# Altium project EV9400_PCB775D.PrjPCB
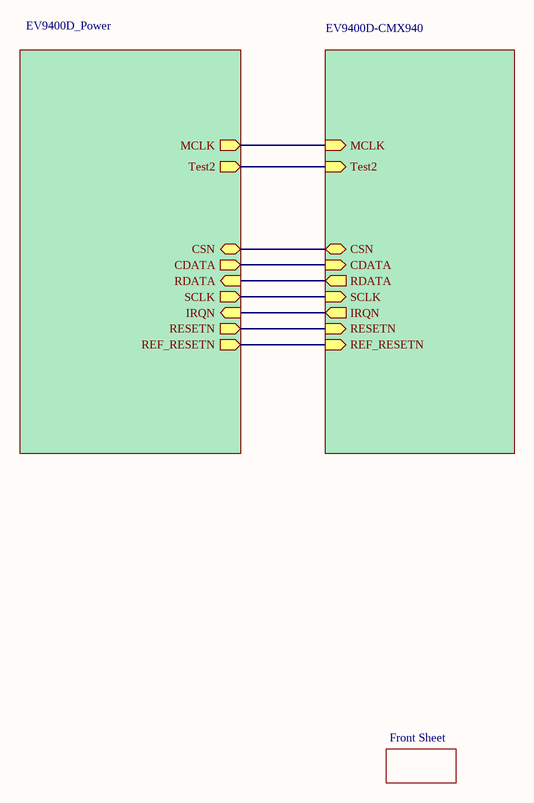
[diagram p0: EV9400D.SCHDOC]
4 sheets, 203 parts. Net scope: hierarchical (ports join the sheet entries above them; power ports are global).
Board file: EV9400D_PCB775D.PCBDOC
Sheets:
  EV9400D.SCHDOC
    EV9400D_Power = EV9400D_Power.SCHDOC
    EV9400D-CMX940 = EV9400D-CMX940.SCHDOC
    Front Sheet = EV9400D_FrontSheet.SchDoc

## Sheet EV9400D.SCHDOC: EV9400
size A4; Date: 09/04/2020; DrawnBy: RAS; Engineer: JLF; Organization: CML Microcircuits UK Ltd; Revision: D02; SheetNumber: 2; SheetTotal: 4; ModifiedBy: RAS; ProjectNo: z206; PageSetup: Record=PageOptions¦CenterHorizontal=True¦CenterVertical=True¦PrintScale=0.71¦XCorrection=1.00¦YCorrection=1.00¦PrintKind=1¦BorderSize=5000000¦LeftOffset=0¦BottomOffset=0¦Orientation=2¦PaperLength=1000¦PaperWidth=1000¦Scale=100¦PaperSource=15¦PrintQuality=600¦MediaType=1¦DitherType=10¦PaperKind=A3¦PrintScaleMode=1

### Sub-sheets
EV9400D-CMX940 = EV9400D-CMX940.SCHDOC: MCLK (in), CSN, CDATA (in), RDATA (out), SCLK (in), IRQN (out), RESETN (in), REF_RESETN (in), Test2 (in)
EV9400D_Power = EV9400D_Power.SCHDOC: MCLK (out), CSN, CDATA (out), RDATA (in), SCLK (out), IRQN (in), RESETN (out), REF_RESETN (out), Test2 (out)
Front Sheet = EV9400D_FrontSheet.SchDoc: no entries

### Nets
CDATA: sheet EV9400D_Power/CDATA, sheet EV9400D-CMX940/CDATA
CSN: sheet EV9400D_Power/CSN, sheet EV9400D-CMX940/CSN
IRQN: sheet EV9400D_Power/IRQN, sheet EV9400D-CMX940/IRQN
MCLK: sheet EV9400D_Power/MCLK, sheet EV9400D-CMX940/MCLK
RDATA: sheet EV9400D_Power/RDATA, sheet EV9400D-CMX940/RDATA
REF_RESETN: sheet EV9400D_Power/REF_RESETN, sheet EV9400D-CMX940/REF_RESETN
RESETN: sheet EV9400D_Power/RESETN, sheet EV9400D-CMX940/RESETN
SCLK: sheet EV9400D_Power/SCLK, sheet EV9400D-CMX940/SCLK
Test2: sheet EV9400D_Power/Test2, sheet EV9400D-CMX940/Test2

## Sheet EV9400D_Power.SCHDOC: EV9400 Power
size A3; Date: 09/04/2020; DrawnBy: RAS; Engineer: JLF; Organization: CML Microcircuits UK Ltd; Revision: D02; SheetNumber: 3; SheetTotal: 4; ModifiedBy: RAS; ProjectNo: z206; PageSetup: Record=PageOptions¦CenterHorizontal=True¦CenterVertical=True¦PrintScale=1.02¦XCorrection=1.00¦YCorrection=1.00¦PrintKind=1¦BorderSize=5000000¦LeftOffset=0¦BottomOffset=0¦Orientation=2¦PaperLength=5940¦PaperWidth=4200¦Scale=100¦PaperSource=7¦PrintQuality=600¦MediaType=1¦DitherType=10¦PaperKind=A2¦PrintScaleMode=1
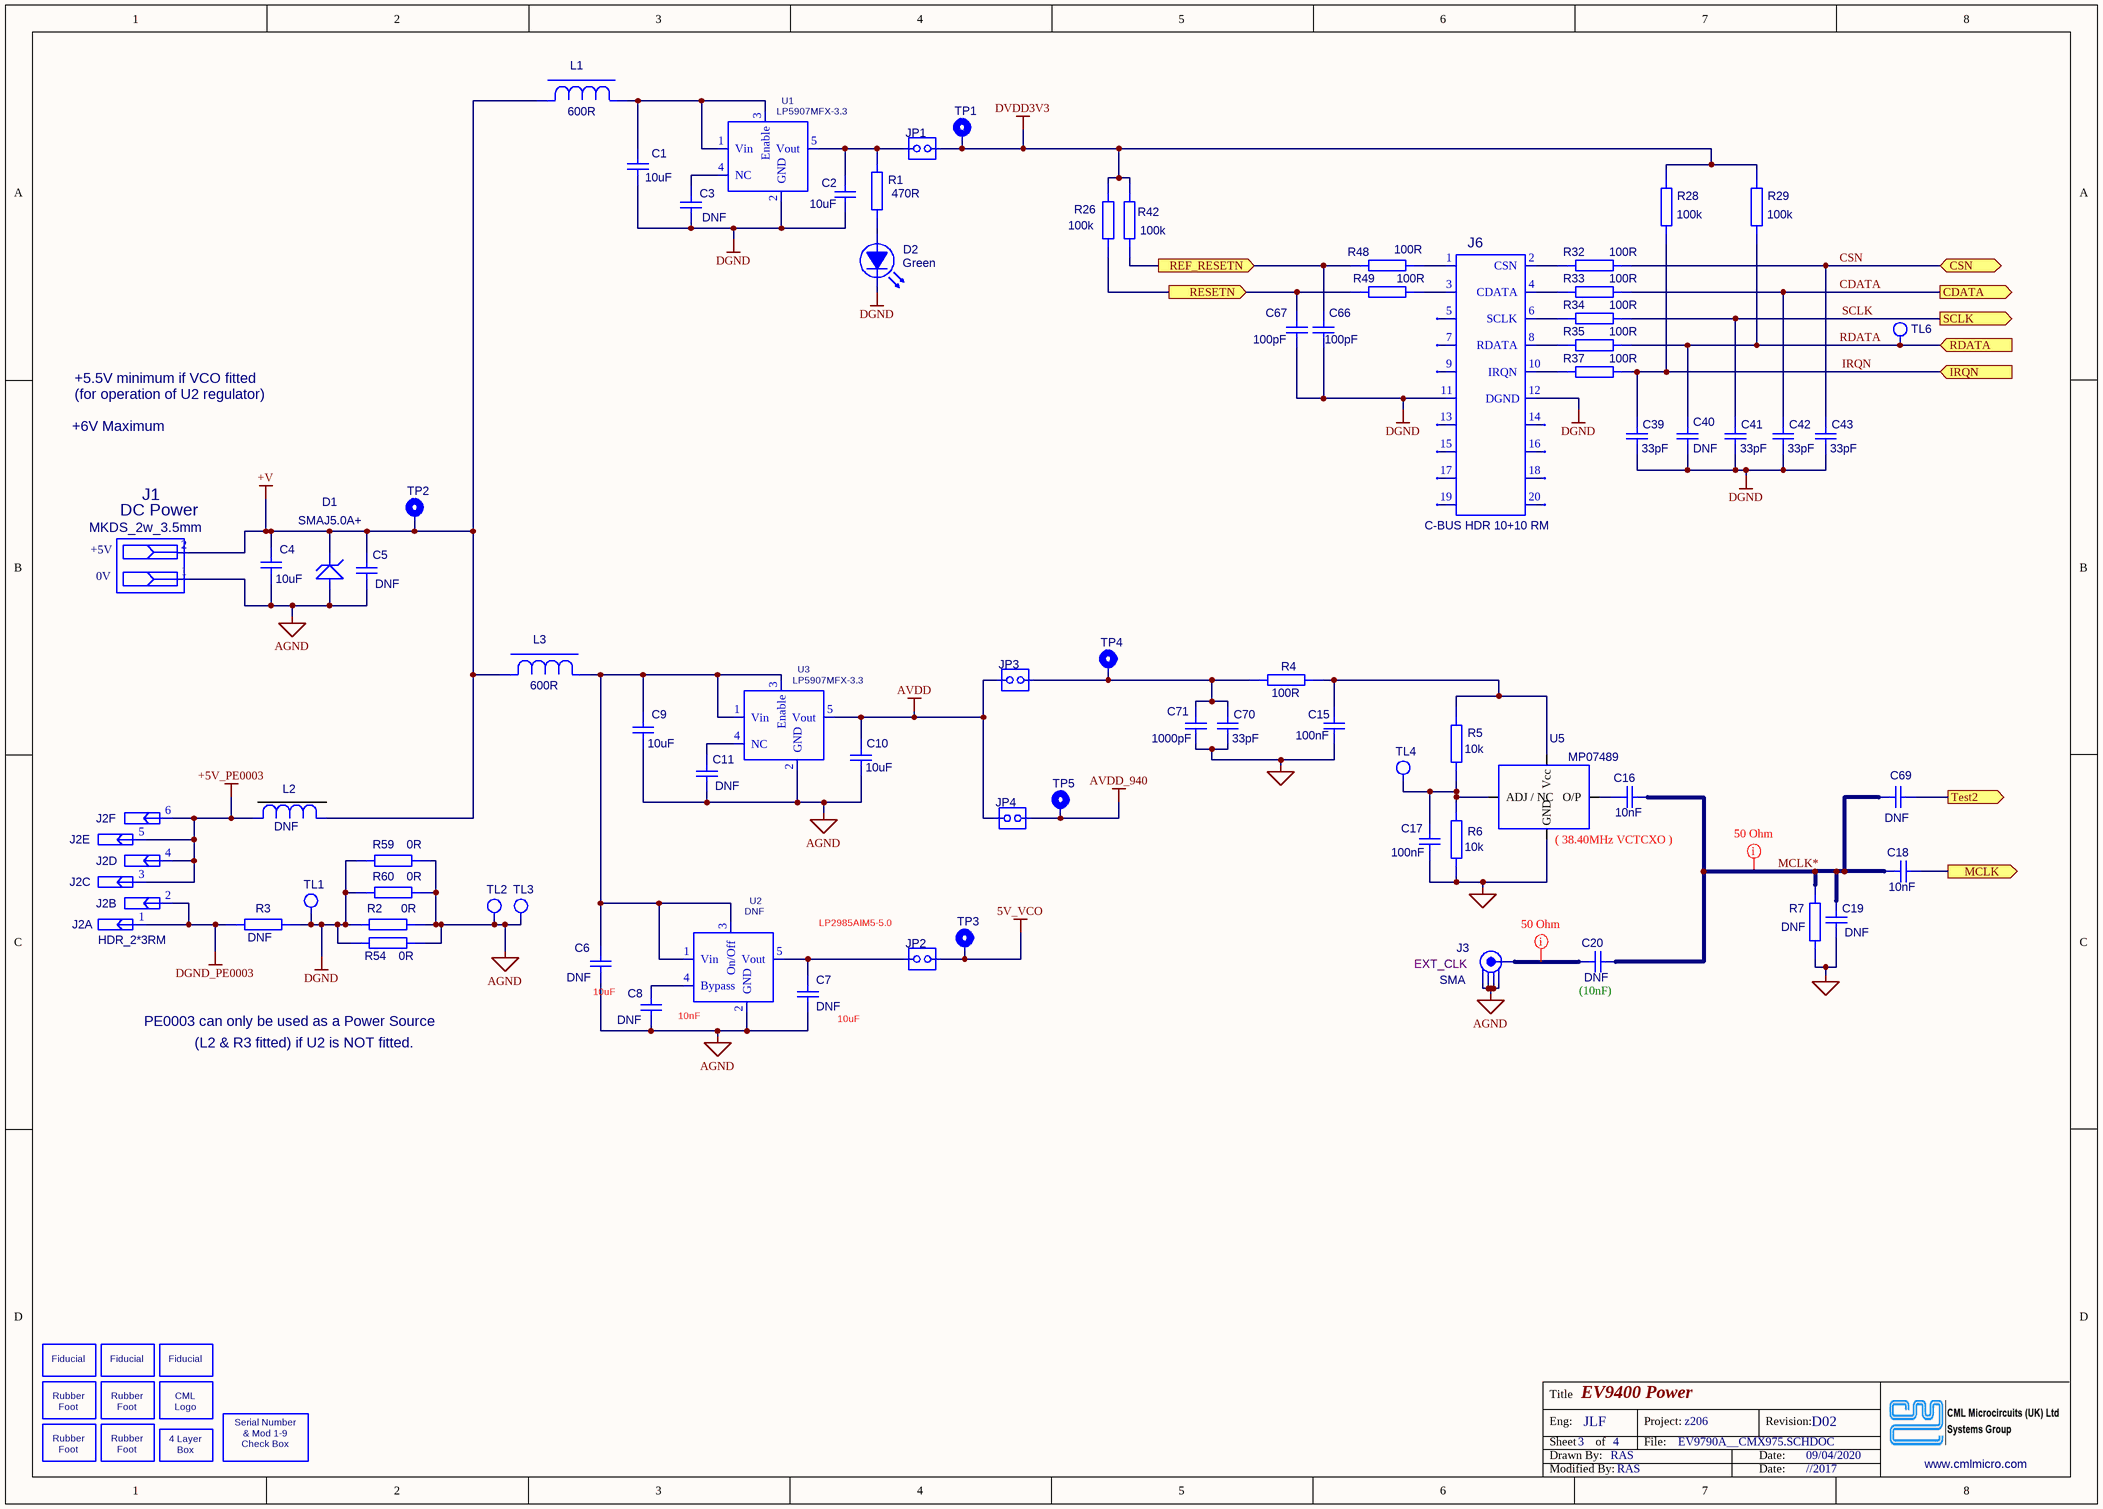
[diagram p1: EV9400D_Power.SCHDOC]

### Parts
C1  10uF  [0805COM]
C2  10uF  [0805COM]
C3  DNF  [0402COM]
C4  10uF  [0805COM]
C5  DNF  [0805COM]
C6  DNF  [0805COM]
C7  DNF  [0805COM]
C8  DNF  [0402COM]
C9  10uF  [0805COM]
C10  10uF  [0805COM]
C11  DNF  [0402COM]
C15  100nF  [0402COM]
C16  10nF  [0402COM]
C17  100nF  [0402COM]
C18  10nF  [0402COM]
C19  DNF  [0402COM]
C20  DNF  [0402COM]
C39  33pF  [0402COM]
C40  DNF  [0402COM]
C41  33pF  [0402COM]
C42  33pF  [0402COM]
C43  33pF  [0402COM]
C66  100pF  [0402COM]
C67  100pF  [0402COM]
C69  DNF  [0402COM]
C70  33pF  [0402COM]
C71  1000pF  [0402COM]
D1  SMAJ5.0A+  [DO-214AC SMA]
D2  Green  [LED0603]
FID1  Fiducial  [1.5MM Fiducial]  (value not drawn)  (no BOM)
FID2  Fiducial  [1.5MM Fiducial]  (value not drawn)  (no BOM)
FID3  Fiducial  [1.5MM Fiducial]  (value not drawn)  (no BOM)
FOOT1  Foot  [FOOT]  (value not drawn)
FOOT2  Foot  [FOOT]  (value not drawn)
FOOT3  Foot  [FOOT]  (value not drawn)
FOOT4  Foot  [FOOT]  (value not drawn)
J1  MKDS_2w_3.5mm  [MKDS_2]
J2  HDR_2*3RM  [IDC6RM]  (value not drawn)  (parts A,B,C,D,E,F of 6)
J3  SMA  SignalName: EXT_CLK  [SMA]
J6  C-BUS HDR 10+10 RM  [IDC20RM]
JP1  Jumper2  [JMP2]  (value not drawn)
JP2  DNF  [JMP2]  (value not drawn)  (no BOM)
JP3  Jumper2  [JMP2]  (value not drawn)
JP4  Jumper2  [JMP2]  (value not drawn)
L1  600R  [0603COM]
L2  DNF  [0603COM]
L3  600R  [0603COM]
LAY1  4_LAYER_BOX  [4_LAYER_BOX]  (value not drawn)  (no BOM)
LOGO1  CML_LOGO  [CML_LOGO]  (value not drawn)  (no BOM)
MODBO1  8 Mod Box  [SERIAL_AND_MOD]  (value not drawn)  (no BOM)
P1  PCB Pad  [TINYPAD]  (value not drawn)  (no BOM)
P2  PCB Pad  [TINYPAD]  (value not drawn)  (no BOM)
P3  PCB Pad  [TINYPAD]  (value not drawn)  (no BOM)
P4  PCB Pad  [TINYPAD]  (value not drawn)  (no BOM)
P5  PCB Pad  [TINYPAD]  (value not drawn)  (no BOM)
P6  PCB Pad  [TINYPAD]  (value not drawn)  (no BOM)
P7  PCB Pad  [TINYPAD]  (value not drawn)  (no BOM)
P8  PCB Pad  [TINYPAD]  (value not drawn)  (no BOM)
P9  PCB Pad  [TINYPAD]  (value not drawn)  (no BOM)
P10  PCB Pad  [TINYPAD]  (value not drawn)  (no BOM)
P11  PCB Pad  [TINYPAD]  (value not drawn)  (no BOM)
R1  470R  [0402COM]
R2  0R  [0402COM]
R3  DNF  [0402COM]
R4  100R  [0402COM]
R5  10k  [0402COM]
R6  10k  [0402COM]
R7  DNF  [0402COM]
R26  100k  [0402COM]
R28  100k  [0402COM]
R29  100k  [0402COM]
R32  100R  [0402COM]
R33  100R  [0402COM]
R34  100R  [0402COM]
R35  100R  [0402COM]
R37  100R  [0402COM]
R42  100k  [0402COM]
R48  100R  [0402COM]
R49  100R  [0402COM]
R54  0R  [0402COM]
R59  0R  [0402COM]
R60  0R  [0402COM]
TL1  1.5mm testloop (Y)  [TESTLOOP_1.0MM]  (value not drawn)
TL2  1.5mm testloop (Y)  [TESTLOOP_1.0MM]  (value not drawn)
TL3  1.5mm testloop (Y)  [TESTLOOP_1.0MM]  (value not drawn)
TL4  1.5mm testloop (Y)  [TESTLOOP_1.0MM]  (value not drawn)
TL6  1.5mm testloop (Y)  [TESTLOOP_1.0MM]  (value not drawn)
TP1  DVDD3V3  [1.5MM TSTPOINTV]  (value not drawn)  (no BOM)
TP2  +V  [1.5MM TSTPOINTV]  (value not drawn)  (no BOM)
TP3  5V_VCO  [1.5MM TSTPOINTV]  (value not drawn)  (no BOM)
TP4  AVDD  [1.5MM TSTPOINTV]  (value not drawn)  (no BOM)
TP5  AVDD_940  [1.5MM TSTPOINTV]  (value not drawn)  (no BOM)
U1  LP5907MFX-3.3  [SOT23-5]
U2  DNF  [SOT23-5]  (no BOM)
U3  LP5907MFX-3.3  [SOT23-5]
U5  MP07489  [GTXO-74]

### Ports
CDATA (out), CSN, IRQN (in), MCLK (out), RDATA (in), REF_RESETN (out), RESETN (out), SCLK (out), Test2 (out)

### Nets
5V_VCO: JP2.2 TP3.1
+5V_PE0003: J2.3 J2.4 J2.5 J2.6 L2.1
+V: C4.2 C5.2 D1.1(K) J1.2 L1.1 L2.2 L3.1 TP2.1
AGND: C4.1 C5.1 C6.1 C7.2 C8.2 C9.1 C10.2 C11.2 C15.2 C17.1 C19.2 C70.2 C71.2 D1.2(A) J1.1 J3.2(GND) J3.3(GND) J3.4(GND) J3.5(GND) R2.1 R6.2 R7.1 R54.1 R59.1 R60.1 TL2.1 TL3.1 U2.2(GND) U3.2(GND) U5.2(GND)
AVDD: C10.1 JP3.1 JP4.1 U3.5(Vout)
AVDD_940: JP4.2 TP5.1
DGND: C1.1 C2.2 C3.2 C39.2 C40.2 C41.2 C42.2 C43.2 C66.2 C67.2 D2.2(Cathode) J6.11(DGND) J6.12(DGND) R2.2 R3.1 R54.2 R59.2 R60.2 TL1.1 U1.2(GND)
DGND_PE0003: J2.1 J2.2 R3.2
DVDD3V3: JP1.2 R26.2 R28.2 R29.2 R42.2 TP1.1
CDATA: C42.1 R33.1 ; port CDATA
CSN: C43.1 R32.1 ; port CSN
IRQN: C39.1 R28.1 R37.1 ; port IRQN
MCLK: C18.2 ; port MCLK
MCLK*: C16.2 C18.1 C19.1 C20.2 C69.1 R7.2
RDATA: C40.1 R29.1 R35.1 TL6.1 ; port RDATA
REF_RESETN: C66.1 R42.1 R48.2 ; port REF_RESETN
RESETN: C67.1 R26.1 R49.2 ; port RESETN
SCLK: C41.1 R34.1 ; port SCLK
Test2: C69.2 ; port Test2
NetC1_2: C1.2 L1.2 U1.1(Vin) U1.3(Enable)
NetC2_1: C2.1 JP1.1 R1.1 U1.5(Vout)
NetC3_1: C3.1 U1.4(NC)
NetC6_2: C6.2 C9.2 L3.2 U2.1(Vin) U2.3(On/Off) U3.1(Vin) U3.3(Enable)
NetC7_1: C7.1 JP2.1 U2.5(Vout)
NetC8_1: C8.1 U2.4(Bypass)
NetC11_1: C11.1 U3.4(NC)
NetC15_1: C15.1 R4.1 R5.1 U5.4(Vcc)
NetC16_1: C16.1 U5.3(O/P)
NetC17_2: C17.2 R5.2 R6.1 TL4.1 U5.1(ADJ_/_NC)
NetC20_1: C20.1 J3.1(SIG)
NetC70_1: C70.1 C71.1 JP3.2 R4.2 TP4.1
NetD2_1: D2.1(Anode) R1.2
NetJ6_1: J6.1 R48.1
NetJ6_2: J6.2(CSN) R32.2
NetJ6_3: J6.3 R49.1
NetJ6_4: J6.4(CDATA) R33.2
NetJ6_5: J6.5 P1.1
NetJ6_6: J6.6(SCLK) R34.2
NetJ6_7: J6.7 P2.1
NetJ6_8: J6.8(RDATA) R35.2
NetJ6_9: J6.9 P3.1
NetJ6_10: J6.10(IRQN) R37.2
NetJ6_13: J6.13 P4.1
NetJ6_14: J6.14 P11.1
NetJ6_15: J6.15 P5.1
NetJ6_16: J6.16 P10.1
NetJ6_17: J6.17 P6.1
NetJ6_18: J6.18 P9.1
NetJ6_19: J6.19 P7.1
NetJ6_20: J6.20 P8.1

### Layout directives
net class 50 Ohm: MCLK*, NetC20_1

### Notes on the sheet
- +5.5V minimum if VCO fitted
- +6V Maximum
- (for operation of U2 regulator)
- (near J1) DC Power
- +5V
- 0V
- (near U5) ( 38.40MHz VCTCXO )
- (near U2) LP2985AIM5-5.0
- (near J3) EXT_CLK
- PE0003 can only be used as a Power Source
- (L2 & R3 fitted) if U2 is NOT fitted.
- (near C6) 10uF
- (near C8) 10nF
- (near C7) 10uF
- (near C20) (10nF)

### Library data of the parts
C1 C2 C4 C9 C10 = CAP0805_10000000_X7R_10V_±10%: 0805 Cer. Cap. 10uF±10% 10V X7R; Part Number: CAP262; WhenFit: SMT Capacitor; Checked: no; TGMC P/N: MML203-1005; Tolerance: 10%; ExpValUnit: pF
C3 C8 C11 C19 C20 C40 C69 = CAP0402_DNF: Pads for 0402 Ceramic Capacitor; WhenFit: DNF; Checked: no; ExpValue: PCB Pads
C5-C7 = CAP0805_DNF: Unused pads for 0805 Ceramic Capacitor; WhenFit: DNF; Checked: no; ExpValue: PCB Pads
C15 C17 = CAP0402_100000_X7R_16V_±10%: 0402 Cer. Cap. 100nF 16V X7R ±10%; Part Number: CAP237; WhenFit: SMT Cap; Checked: no; ExpValue: 100000; ExpValUnit: pF
C16 C18 = CAP0402_10000_X7R_25V_±10%: 0402 Cer. Cap. 10nF 25V X7R ±10%; Part Number: CAP228; WhenFit: SMT Cap; Checked: no; ExpValue: 10000; TGMC P/N: 201-1002; ExpValUnit: pF
C39 C41-C43 C70 = CAP0402_33p±5%_C0G_25V: 0402 Cer. Cap. 33pF±5% 25V C0G; Part Number: CAP199; WhenFit: SMT Cap; Checked: no; Dielectric: C0G/NP0; ExpValue: 33; Tolerance: 5%; ExpValUnit: pF
C66 C67 = CAP0402_100p_C0G_25V_± 5%: 0402 Cer. Cap. 100pF±5% 25V C0G; Part Number: CAP205; WhenFit: SMT Cap; Checked: no; Dielectric: C0G/NP0; ExpValue: 100; TGMC P/N: 201-1000; Tolerance: 5%; ExpValUnit: pF
C71 = CAP0402_1000_C0G_25V_± 5%: 0402 Cer. Cap. 1000pF±5% 25V C0G; Part Number: CAP219; WhenFit: SMT Cap; Checked: no; Dielectric: C0G/NP0; ExpValue: 1000; Tolerance: 5%; ExpValUnit: pF
D1 = SMAJ5_0A: 5V Transient Suppression Diode, DO-214AC; Part Number: DSM083; WhenFit: SMT Other; Checked: no
D2 = LED0603_Green: Green 0603 LED, KPT-1608CGCK; Part Number: OPT011; WhenFit: SMT Other; Checked: no
FID1-FID3 = Fiducial: 1.5mm round pad Fiducial; Checked: no
FOOT1-FOOT4 = FOOT: 12.7mm square stick-on foot; Part Number: FIX006; WhenFit: After Wash
J1 = MKDS_2w_3_5mm: 2-WAY PCB screw terminal block - MKDS 1/ 2-3,5 HT BK; Part Number: CON126; Manuf P/N: 1985807; WhenFit: After Wash; Checked: no
J2 = HDR_2*3RM: 3+3 double row 0.1in header right angle; Part Number: CON082; Manuf P/N: TSW-103-08-G-D-RA; WhenFit: PTH; Checked: no
J3 = SMA_STRAIGHT: PCB Mounted SMA Socket (Upright); Part Number: CON046; Manuf P/N: 5-1814832-1; WhenFit: PTH; Checked: no
J6 = HDR_10*2_CBUS_RM: C-BUS R/A Male Header; Part Number: CON057; WhenFit: PTH; Checked: no
JP1 JP3 JP4 = JUMPER2: Pin header 2X1; Part Number: CON005; WhenFit: PTH; Checked: no; SignalName: {SignalName}
JP2 = JUMPER2_DNF: Holes for Pin header 2X1; WhenFit: DNF; Checked: no
L1 L3 = Ferrite 0603_600R: Ferrite, 0603, 600R @ 100MHz 1.3A; Part Number: TRF089; WhenFit: SMT Other; Checked: no; ExpValue: 600; TGMC P/N: ATL300-0001
L2 = IND0603HP_DNF: Pads for Coilcraft 0603 Inductor; WhenFit: SMT Inductor; Checked: no; ExpValue: PCB Pads; ExpValUnit: nH
LAY1 = 4_LAYER_BOX: Checked: no; Value: 4 Layer PCB
MODBO1 = SERIAL_AND_MODBOX
P1-P11 = TINY_PAD: Very Small Pad - used to remove all of the 'unconnected pin' errors from ERC & DRC; Checked: no; SignalName: {SignalName}
R1 = R0402_470R: Resistor 0402 470R 1% 0.063W  ( 66A = 475R ); Part Number: RES265; WhenFit: SMT Resistor; Checked: no; ExpValue: 470; TGMC P/N: 101-4700; ExpValUnit: Ohm
R2 R54 R59 R60 = R0402_0R: Resistor 0402 0R 0.063W; Part Number: RES199; WhenFit: SMT Resistor; Checked: no; ExpValue: 0; ExpValUnit: Ohm
R3 R7 = R0402_DNF: Pads for Resistor 0402; WhenFit: DNF; Checked: no; ExpValue: PCB Pads; ExpValUnit: Tx/Rx
R4 = R0402_100R: Resistor 0402 100R 1% 0.063W  ( 01A ); Part Number: RES248; WhenFit: SMT Resistor; Checked: no; ExpValue: 100; ExpValUnit: Ohm
R5 = R0402_10000_10k: Resistor 0402 10k 1% 0.063W  ( 01C ); Part Number: RES297; WhenFit: SMT Resistor; Checked: no; ExpValue: 10000; ExpValUnit: Ohm
R6 = R0402_10000_10k: Resistor 0402 10k 1% 0.063W  ( 01C ); Part Number: RES297; WhenFit: SMT Resistor; Checked: no; ExpValue: 10000; TGMC P/N: 101-1002; ExpValUnit: Ohm
R26 R28 R29 R42 = R0402_100000_100k: Resistor 0402 100k 1% 0.063W  ( O1D ); Part Number: RES322; WhenFit: SMT Resistor; Checked: no; ExpValue: 100000; TGMC P/N: 101-1003; ExpValUnit: Ohm
R32-R35 R37 R48 R49 = R0402_100R: Resistor 0402 100R 1% 0.063W  ( 01A ); Part Number: RES248; WhenFit: SMT Resistor; Checked: no; ExpValue: 100; TGMC P/N: 101-1000; ExpValUnit: Ohm
TL1 = TESTLOOP_1MM: Yellow 1.5mm testloop (1.0 mm hole); Part Number: CON108; WhenFit: PTH; Checked: no; SignalName: DGND
TL2 TL3 = TESTLOOP_1MM: Yellow 1.5mm testloop (1.0 mm hole); Part Number: CON108; WhenFit: PTH; Checked: no; SignalName: AGND
TL4 TL6 = TESTLOOP_1MM: Yellow 1.5mm testloop (1.0 mm hole); Part Number: CON108; WhenFit: PTH; Checked: no; SignalName: {SignalName}
TP1-TP5 = 1.5MM TSTPOINTV: 1.5mm Testpoint with via; Value: PCB Pad; WhenFit: DNF; Checked: no
U1 U3 = LP5907MFX-3.3: LP5907MFX-3.3,   3.3V, 250mA ULN Low-IQ LDO Regulator, SOT23-5; Part Number: ICS165; WhenFit: SMT Other; Checked: no; Marking: LLVB; Alternative: 595-LP5907QMFX-3.3Q1  (RAHQ)
U2 = LP2985_DNF: Pads for LP2985 regulator, SOT23-5; WhenFit: DNF; Checked: no
U5 = MP07489: 38.40MHz GTXO-74V/JI SM Sine VCTCXO 2.5ppm; Part Number: XTL041; Checked: no; WhenFit: SMT Other

## Sheet EV9400D-CMX940.SCHDOC: EV9400 CMX940
size A3; Date: 09/04/2020; DrawnBy: RAS; Engineer: JLF; Organization: CML Microcircuits UK Ltd; Revision: D02; SheetNumber: 4; SheetTotal: 4; ModifiedBy: RAS; ProjectNo: z206; PageSetup: Record=PageOptions|CenterHorizontal=True|CenterVertical=True|PrintScale=2.04|XCorrection=1.00|YCorrection=1.00|PrintKind=1|BorderSize=5000000|LeftOffset=0|BottomOffset=0|Orientation=2|PaperLength=8410|PaperWidth=5940|Scale=100|PaperSource=7|PrintQuality=600|MediaType=1|DitherType=10|PaperKind=A1|PrintScaleMode=1
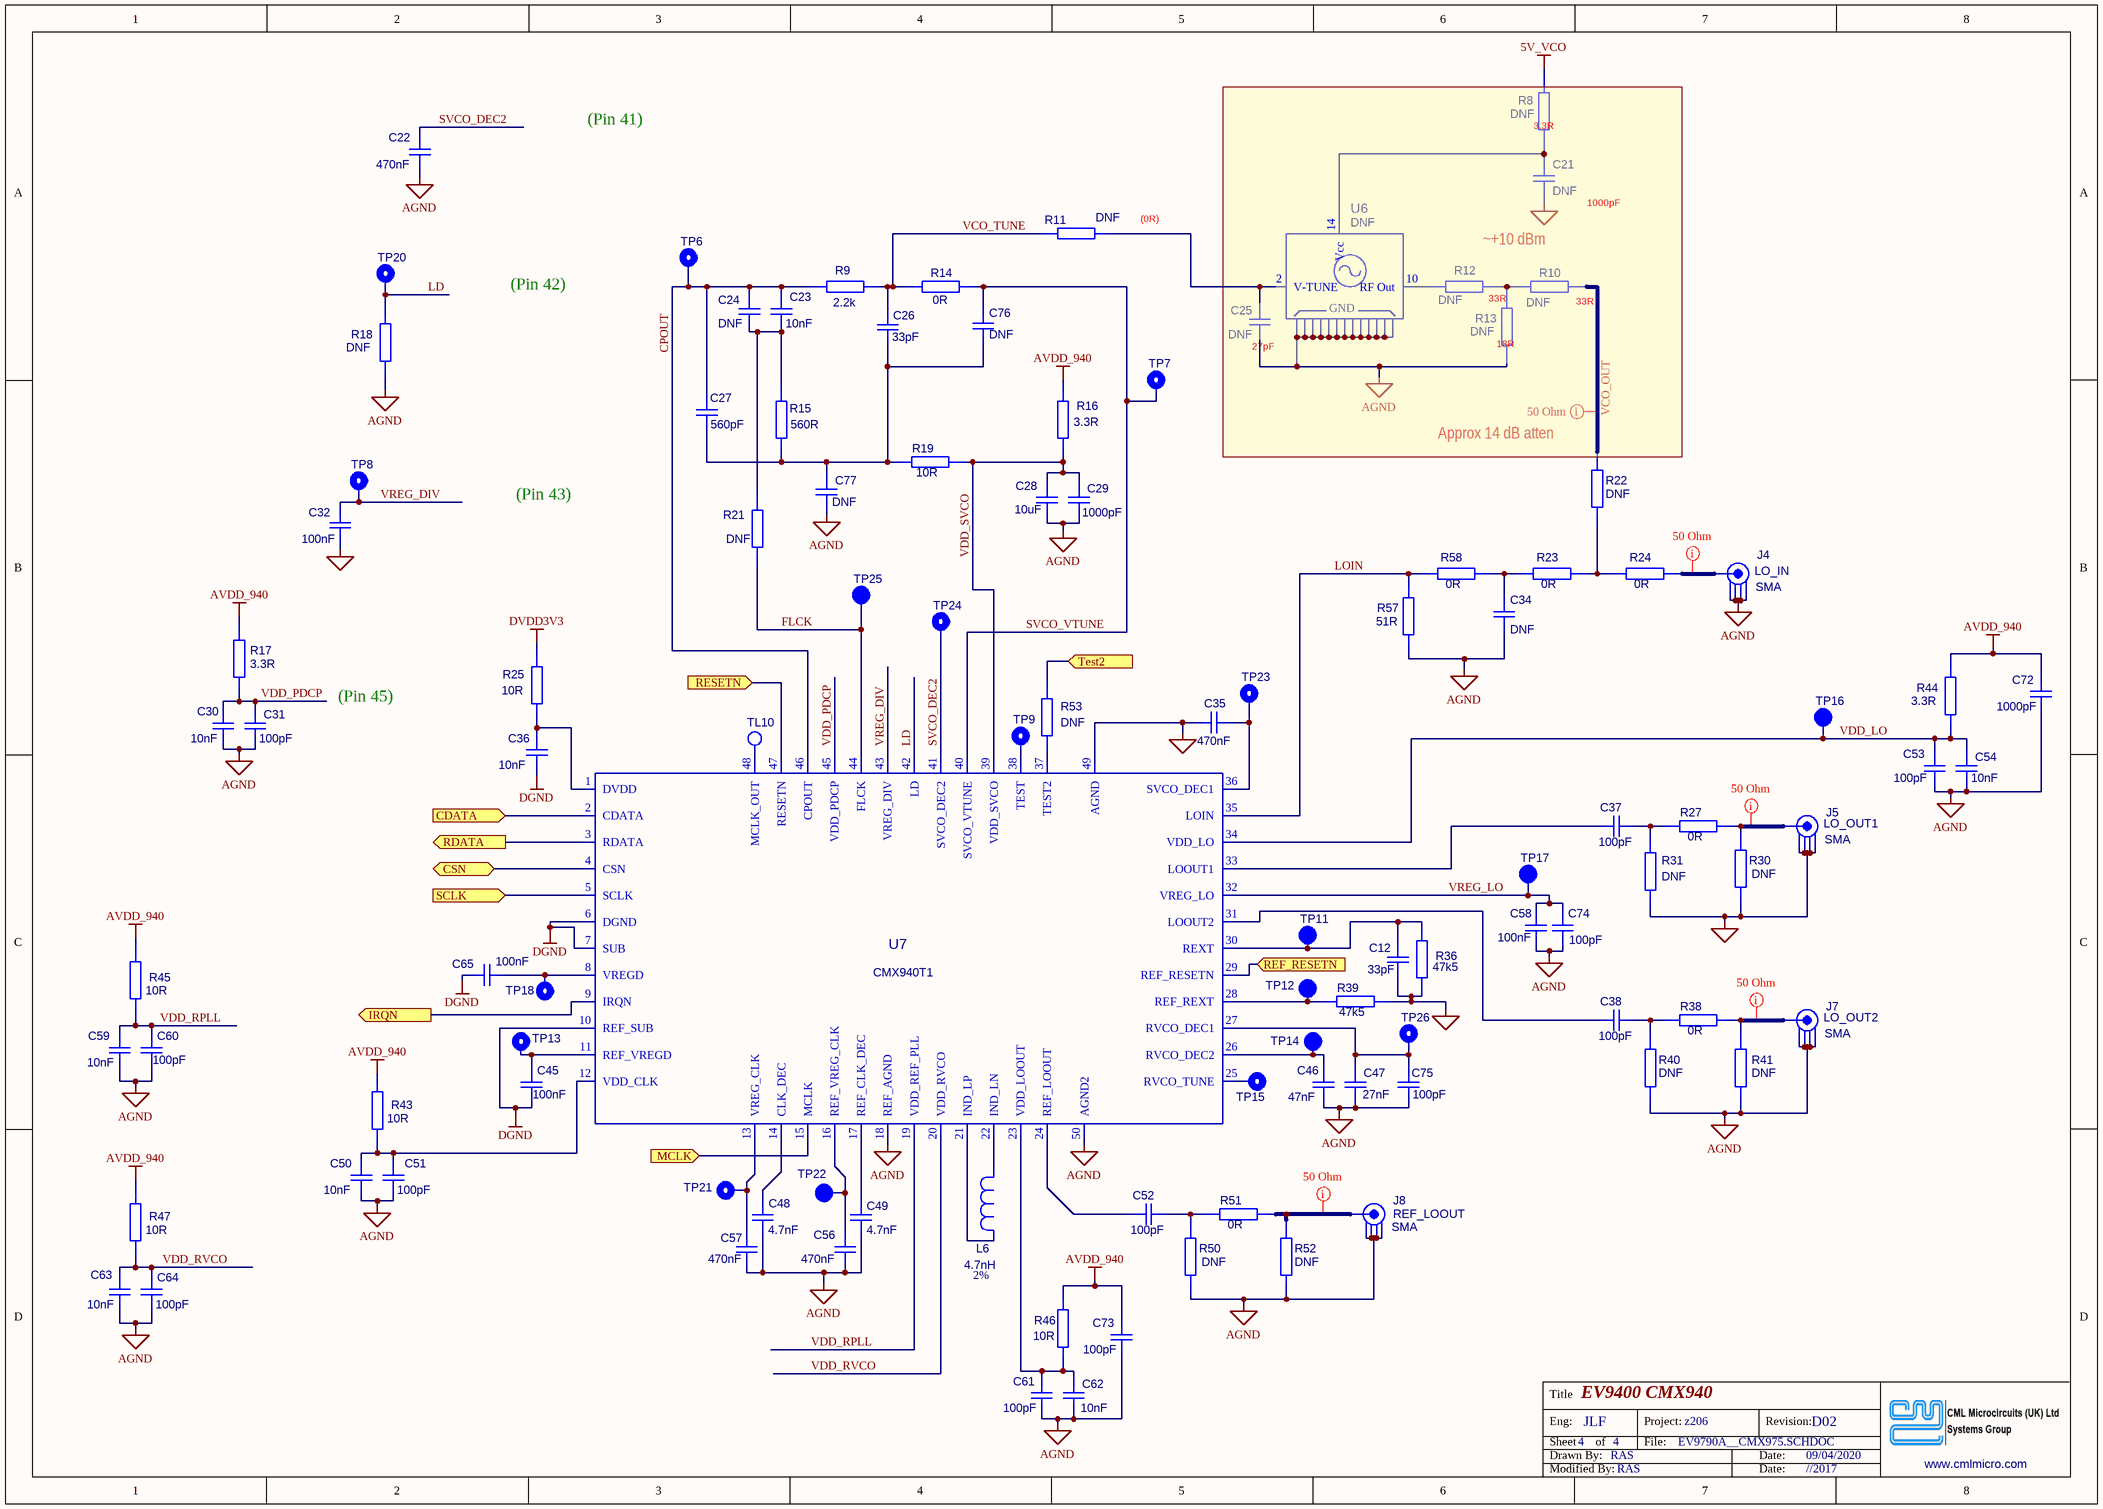
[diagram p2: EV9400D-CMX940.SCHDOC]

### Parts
C12  33pF  [0402COM]
C21  DNF  [0402COM]
C22  470nF  [0402COM]
C23  10nF  [0402COM]
C24  DNF  [0402COM]
C25  DNF  [0402COM]
C26  33pF  [0402COM]
C27  560pF  [0402COM]
C28  10uF  [0402COM]
C29  1000pF  [0402COM]
C30  10nF  [0402COM]
C31  100pF  [0402COM]
C32  100nF  [0402COM]
C34  DNF  [0402COM]
C35  470nF  [0402COM]
C36  10nF  [0402COM]
C37  100pF  [0402COM]
C38  100pF  [0402COM]
C45  100nF  [0402COM]
C46  47nF  [0402COM]
C47  27nF  [0402COM]
C48  4.7nF  [0402COM]
C49  4.7nF  [0402COM]
C50  10nF  [0402COM]
C51  100pF  [0402COM]
C52  100pF  [0402COM]
C53  100pF  [0402COM]
C54  10nF  [0402COM]
C56  470nF  [0402COM]
C57  470nF  [0402COM]
C58  100nF  [0402COM]
C59  10nF  [0402COM]
C60  100pF  [0402COM]
C61  100pF  [0402COM]
C62  10nF  [0402COM]
C63  10nF  [0402COM]
C64  100pF  [0402COM]
C65  100nF  [0402COM]
C72  1000pF  [0402COM]
C73  100pF  [0402COM]
C74  100pF  [0402COM]
C75  100pF  [0402COM]
C76  DNF  [0402COM]
C77  DNF  [0402COM]
J4  SMA  SignalName: LO_IN  [SMA]
J5  SMA  SignalName: LO_OUT1  [SMA]
J7  SMA  SignalName: LO_OUT2  [SMA]
J8  SMA  SignalName: REF_LOOUT  [SMA]
L6  4.7nH  Tolerance: 2%  [0402COM]
R8  DNF  [0402COM]
R9  2.2k  [0402COM]
R10  DNF  [0402COM]
R11  DNF  [0402COM]
R12  DNF  [0402COM]
R13  DNF  [0402COM]
R14  0R  [0402COM]
R15  560R  [0402COM]
R16  3.3R  [0402COM]
R17  3.3R  [0402COM]
R18  DNF  [0402COM]
R19  10R  [0402COM]
R21  DNF  [0402COM]
R22  DNF  [0402COM]
R23  0R  [0402COM]
R24  0R  [0402COM]
R25  10R  [0402COM]
R27  0R  [0402COM]
R30  DNF  [0402COM]
R31  DNF  [0402COM]
R36  47k5  [0402COM]
R38  0R  [0402COM]
R39  47k5  [0402COM]
R40  DNF  [0402COM]
R41  DNF  [0402COM]
R43  10R  [0402COM]
R44  3.3R  [0402COM]
R45  10R  [0402COM]
R46  10R  [0402COM]
R47  10R  [0402COM]
R50  DNF  [0402COM]
R51  0R  [0402COM]
R52  DNF  [0402COM]
R53  DNF  [0402COM]
R57  51R  [0402COM]
R58  0R  [0402COM]
TL10  (no value)  [TESTLOOP_1.0MM]  (no BOM)
TP6  MCLK_OUT  [0.8MM_ATE_TSTPT]  (value not drawn)  (no BOM)
TP7  SVCO_VTUNE  [0.8MM_ATE_TSTPT]  (value not drawn)  (no BOM)
TP8  VREG_DIV  [0.8MM_ATE_TSTPT]  (value not drawn)  (no BOM)
TP9  TEST  [0.8MM_ATE_TSTPT]  (value not drawn)  (no BOM)
TP11  REXT  [0.8MM ATETSTPT-SL]  (value not drawn)  (no BOM)
TP12  REF_REXT  [0.8MM ATETSTPT-SL]  (value not drawn)  (no BOM)
TP13  REF_VREGD  [0.8MM_ATE_TSTPT]  (value not drawn)  (no BOM)
TP14  RVCO_DEC2  [0.8MM ATETSTPT-SL]  (value not drawn)  (no BOM)
TP15  MCLK_OUT  [0.8MM_ATE_TSTPT]  (value not drawn)  (no BOM)
TP16  VDD_LO  [0.8MM ATETSTPT-SL]  (value not drawn)  (no BOM)
TP17  VREG_LO  [0.8MM ATETSTPT-SL]  (value not drawn)  (no BOM)
TP18  VREGD  [0.8MM_ATE_TSTPT]  (value not drawn)  (no BOM)
TP20  LD  [0.8MM_ATE_TSTPT]  (value not drawn)  (no BOM)
TP21  VREG_CLK  [0.8MM_ATE_TSTPT]  (value not drawn)  (no BOM)
TP22  REF_VREG_CLK  [0.8MM ATETSTPT-SL]  (value not drawn)  (no BOM)
TP23  SVCO_DEC1  [0.8MM_ATE_TSTPT]  (value not drawn)  (no BOM)
TP24  SVCO_DEC2  [0.8MM_ATE_TSTPT]  (value not drawn)  (no BOM)
TP25  FLCK  [0.8MM ATETSTPT-SL]  (value not drawn)  (no BOM)
TP26  RVCO_DEC1  [0.8MM_ATE_TSTPT]  (value not drawn)  (no BOM)
U6  DNF  [PL-012]  (no BOM)
U7  CMX940T1  [QFN50P700X700X110_HS-50N]

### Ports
CDATA (in), CSN, IRQN (out), MCLK (in), RDATA (out), REF_RESETN (in), RESETN (in), SCLK (in), Test2 (in)

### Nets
5V_VCO: R8.1
AGND: C12.2 C21.2 C22.2 C25.2 C28.2 C29.2 C30.2 C31.2 C32.1 C34.2 C35.2 C46.2 C47.2 C48.2 C49.2 C50.2 C51.2 C53.2 C54.2 C56.2 C57.2 C58.2 C59.2 C60.2 C61.2 C62.2 C63.2 C64.2 C72.2 C73.2 C74.2 C75.2 C77.2 J4.2(GND) J4.3(GND) J4.4(GND) J4.5(GND) J5.2(GND) J5.3(GND) J5.4(GND) J5.5(GND) J7.2(GND) J7.3(GND) J7.4(GND) J7.5(GND) J8.2(GND) J8.3(GND) J8.4(GND) J8.5(GND) R13.2 R18.2 R30.1 R31.1 R36.2 R39.2 R40.1 R41.1 R50.1 R52.1 R57.2 U6.1(GND) U6.3(GND) U6.4(GND) U6.5(GND) U6.6(GND) U6.7(GND) U6.8(GND) U6.9(GND) U6.11(GND) U6.12(GND) U6.13(GND) U6.15(GND) U6.16(GND) U7.18(REF_AGND) U7.49(AGND) U7.50(AGND2)
AVDD_940: C72.1 C73.1 R16.2 R17.1 R43.1 R44.1 R45.1 R46.2 R47.1
DGND: C36.2 C45.2 C65.1 U7.6(DGND) U7.7(SUB) U7.10(REF_SUB)
DVDD3V3: R25.2
CDATA: U7.2(CDATA) ; port CDATA
CPOUT: C23.1 C24.1 C27.1 R9.1 TP6.1 U7.46(CPOUT)
CSN: U7.4(CSN) ; port CSN
FLCK: R21.1 TP25.1 U7.44(FLCK)
IRQN: U7.9(IRQN) ; port IRQN
LD: R18.1 TP20.1 U7.42(LD)
LOIN: R57.1 R58.1 U7.35(LOIN)
MCLK: U7.15(MCLK) ; port MCLK
RDATA: U7.3(RDATA) ; port RDATA
REF_RESETN: U7.29(REF_RESETN) ; port REF_RESETN
RESETN: U7.47(RESETN) ; port RESETN
SCLK: U7.5(SCLK) ; port SCLK
SVCO_DEC2: C22.1 TP24.1 U7.41(SVCO_DEC2)
SVCO_VTUNE: C76.2 R14.1 TP7.1 U7.40(SVCO_VTUNE)
Test2: R53.2 ; port Test2
VCO_OUT: R10.1 R22.2
VCO_TUNE: C26.1 R9.2 R11.2 R14.2
VDD_LO: C53.1 C54.1 R44.2 TP16.1 U7.34(VDD_LO)
VDD_PDCP: C30.1 C31.1 R17.2 U7.45(VDD_PDCP)
VDD_RPLL: C59.1 C60.1 R45.2 U7.19(VDD_REF_PLL)
VDD_RVCO: C63.1 C64.1 R47.2 U7.20(VDD_RVCO)
VDD_SVCO: C28.1 C29.1 R16.1 R19.2 U7.39(VDD_SVCO)
VREG_DIV: C32.2 TP8.1 U7.43(VREG_DIV)
VREG_LO: C58.1 C74.1 TP17.1 U7.32(VREG_LO)
NetC12_1: C12.1 R36.1 TP11.1 U7.30(REXT)
NetC21_1: C21.1 R8.2 U6.14(Vcc)
NetC23_2: C23.2 C24.2 R15.1 R21.2
NetC25_1: C25.1 R11.1 U6.2(V-TUNE)
NetC26_2: C26.2 C27.2 C76.1 C77.1 R15.2 R19.1
NetC34_1: C34.1 R23.1 R58.2
NetC35_1: C35.1 TP23.1 U7.36(SVCO_DEC1)
NetC36_1: C36.1 R25.1 U7.1(DVDD)
NetC37_1: C37.1 U7.33(LOOUT1)
NetC37_2: C37.2 R27.1 R31.2
NetC38_1: C38.1 U7.31(LOOUT2)
NetC38_2: C38.2 R38.1 R40.2
NetC45_1: C45.1 TP13.1 U7.11(REF_VREGD)
NetC46_1: C46.1 TP14.1 U7.26(RVCO_DEC2)
NetC47_1: C47.1 C75.1 TP26.1 U7.27(RVCO_DEC1)
NetC48_1: C48.1 U7.14(CLK_DEC)
NetC49_1: C49.1 U7.17(REF_CLK_DEC)
NetC50_1: C50.1 C51.1 R43.2 U7.12(VDD_CLK)
NetC52_1: C52.1 U7.24(REF_LOOUT)
NetC52_2: C52.2 R50.2 R51.1
NetC56_1: C56.1 TP22.1 U7.16(REF_VREG_CLK)
NetC57_1: C57.1 TP21.1 U7.13(VREG_CLK)
NetC61_1: C61.1 C62.1 R46.1 U7.23(VDD_LOOUT)
NetC65_2: C65.2 TP18.1 U7.8(VREGD)
NetJ4_1: J4.1(SIG) R24.2
NetJ5_1: J5.1(SIG) R27.2 R30.2
NetJ7_1: J7.1(SIG) R38.2 R41.2
NetJ8_1: J8.1(SIG) R51.2 R52.2
NetL6_1: L6.1 U7.22(IND_LN)
NetL6_2: L6.2 U7.21(IND_LP)
NetR10_2: R10.2 R12.1 R13.1
NetR12_2: R12.2 U6.10(RF_Out)
NetR22_1: R22.1 R23.2 R24.1
NetR39_1: R39.1 TP12.1 U7.28(REF_REXT)
NetR53_1: R53.1 U7.37(TEST2)
NetTL10_1: TL10.1 U7.48(MCLK_OUT)
NetTP9_1: TP9.1 U7.38(TEST)
NetTP15_1: TP15.1 U7.25(RVCO_TUNE)

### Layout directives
net class 50 Ohm: NetJ4_1, NetJ5_1, NetJ7_1, NetJ8_1, VCO_OUT

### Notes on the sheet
- (Pin 41)
- (near R8) 3.3R
- (near R11) (0R)
- (near U6) ~+10 dBm
- (near C21) 1000pF
- (Pin 42)
- (near R12) 33R
- (near R10) 33R
- (near C25) 27pF
- (near R13) 18R
- Approx 14 dB atten
- (Pin 43)
- (Pin 45)

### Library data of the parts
C12 C26 = CAP0402_33p±5%_C0G_25V: as C39 on sheet EV9400D_Power
C21 C24 C25 C34 C76 C77 = CAP0402_DNF: as C3 on sheet EV9400D_Power
C22 C35 C56 C57 = CAP0402_470000_X5R_10V_±10%: 0402 Cer. Cap. 470nF 10V X5R ±10%; Part Number: CAP240; WhenFit: SMT Cap; Checked: no; ExpValue: 470000; ExpValUnit: pF
C23 C36 C50 C54 C59 C62 C63 = CAP0402_10000_X7R_25V_±10%: as C16 on sheet EV9400D_Power
C27 = CAP0402_560p_C0G_25V_± 5%: 0402 Cer. Cap. 560pF±5% 25V C0G; Part Number: CAP216; WhenFit: SMT Cap; Checked: no; Dielectric: C0G/NP0; ExpValue: 560; Tolerance: 5%; ExpValUnit: pF
C28 = CAP0402_10000000_X5R_6V3_±20%: 0402 Cer. Cap. 10uF 6V3 X5R ±20%; Part Number: CAP244; WhenFit: SMT Cap; Checked: no; ExpValUnit: pF
C29 C72 = CAP0402_1000_C0G_25V_± 5%: as C71 on sheet EV9400D_Power
C30 = CAP0402_10000_X7R_25V_±10%: 0402 Cer. Cap. 10nF 25V X7R ±10%; Part Number: CAP228; WhenFit: SMT Cap; Checked: no; ExpValue: 10000; ExpValUnit: pF
C31 = CAP0402_100p_C0G_25V_± 5%: 0402 Cer. Cap. 100pF±5% 25V C0G; Part Number: CAP205; WhenFit: SMT Cap; Checked: no; Dielectric: C0G/NP0; ExpValue: 100; Tolerance: 5%; ExpValUnit: pF
C32 C45 C58 C65 = CAP0402_100000_X7R_16V_±10%: as C15 on sheet EV9400D_Power
C37 C38 C51-C53 C60 C61 C64 C73-C75 = CAP0402_100p_C0G_25V_± 5%: as C66 on sheet EV9400D_Power
C46 = CAP0402_47000_X7R_25V_±10%: 0402 Cer. Cap. 47nF 25V X7R ±10%; Part Number: CAP234; WhenFit: SMT Cap; Checked: no; ExpValue: 47000; TGMC P/N: 201-4702X; ExpValUnit: pF
C47 = CAP0402_27000_X7R_25V_±10%: 0402 Cer. Cap. 27nF 25V X7R ±10%; Part Number: CAP231; WhenFit: SMT Cap; Checked: no; ExpValue: 27000; ExpValUnit: pF
C48 C49 = CAP0402_4700_X7R_25V_±5%: 0402 Cer. Cap. 4.7nF 25V X7R ±5%; Part Number: CAP274; WhenFit: SMT Cap; Checked: no; ExpValue: 4700; ExpValUnit: pF
J4 J5 J7 J8 = SMA_STRAIGHT: as J3 on sheet EV9400D_Power
L6 = IND0402DC_4n7_2%: 0402 inductor, 4.7nH, 0402DC-4N7XGR; Part Number: TRF146; WhenFit: SMT Inductor; Checked: no; ExpValue: 4.7; ExpValUnit: nH
R8 R10-R13 R18 R21 R22 R30 R31 R40 R41 R50 R52 R53 = R0402_DNF: as R3 on sheet EV9400D_Power
R9 = R0402_2200_2k2: Resistor 0402 2.2k 1% 0.063W  (34B = 2.21k ); Part Number: RES281; WhenFit: SMT Resistor; Checked: no; ExpValue: 2200; ExpValUnit: Ohm
R14 R23 R24 R27 R38 R51 R58 = R0402_0R: Resistor 0402 0R 0.063W; Part Number: RES199; WhenFit: SMT Resistor; Checked: no; ExpValue: 0; TGMC P/N: 101-0000; ExpValUnit: Ohm
R15 = R0402_560R: Resistor 0402 560R 1% 0.063W  ( 73A = 562R ); Part Number: RES267; WhenFit: SMT Resistor; Checked: no; ExpValue: 560; TGMC P/N: 101-5600; ExpValUnit: Ohm
R16 R17 = R0402_3R3: Resistor 0402 3.3R 1% 0.063W   ( 51Y ); Part Number: RES212; WhenFit: SMT Resistor; Checked: no; ExpValue: 3.3; TGMC P/N: 101-0033; ExpValUnit: Ohm
R19 = R0402_10R: Resistor 0402 10R 1% 0.063W   ( 01X ); Part Number: RES224; WhenFit: SMT Resistor; Checked: no; ExpValue: 10; ExpValUnit: Ohm
R25 R43 R45-R47 = R0402_10R: Resistor 0402 10R 1% 0.063W   ( 01X ); Part Number: RES224; WhenFit: SMT Resistor; Checked: no; ExpValue: 10; TGMC P/N: 101-0100; ExpValUnit: Ohm
R36 R39 = R0402_47500_47k5: Resistor 0402 47k5 1% 0.063W  ( 66C = 47.5k ); Part Number: RES314; WhenFit: SMT Resistor; Checked: no; ExpValue: 47500; ExpValUnit: Ohm
R44 = R0402_3R3: Resistor 0402 3.3R 1% 0.063W   ( 51Y ); Part Number: RES212; WhenFit: SMT Resistor; Checked: no; ExpValue: 3.3; ExpValUnit: Ohm
R57 = R0402_51R: Resistor 0402 51R 1% 0.063W  ( 69X = 51.1R ); Part Number: RES241; WhenFit: SMT Resistor; Checked: no; ExpValue: 51; ExpValUnit: Ohm
TL10 = TESTLOOP_1MM_DNF: 1mm hole  for 1.5mm testloop e.g. Rapid  17-1819; Part Number: CON108; WhenFit: PTH; Checked: no; SignalName: MCLK_OUT
TP6 TP7 TP13 TP15 TP18 TP21 TP23 TP24 TP26 = 0.8MM ATE_TSTPT: 0.8mm pad 0.3mm via, 1.27mm spacing circle; Value: PCB Pad; WhenFit: DNF; Checked: no
TP8 TP9 TP20 = 0.8MM ATE_TSTPT: 0.8mm pad 0.3mm via, 1.27mm spacing circle; WhenFit: DNF; Checked: no; Value: PCB Pad
TP11 TP12 TP14 TP16 TP17 TP22 TP25 = 0.8MM ATE_TSTPT_SL: 0.8mm pad top only, 1.27mm spacing circle; Value: PCB Pad; WhenFit: DNF; Checked: no
U6 = VCO_DNF: Pads for 0.5in VCO module; WhenFit: DNF; Checked: No
U7 = CMX940T1: CMX940T1, High Performance Synthesizer; WhenFit: SMT Other; Checked: no

## Sheet EV9400D_FrontSheet.SchDoc: EV9400_Frontsheet
size A3; Date: 17/8/2020; Organization: CML Microcircuits UK Ltd; Revision: D02; SheetNumber: 1; SheetTotal: 4; FSProduct: EV9400; FSIPRDate: 2020; FSDate: 12/11/2020; ModifiedBy: RAS
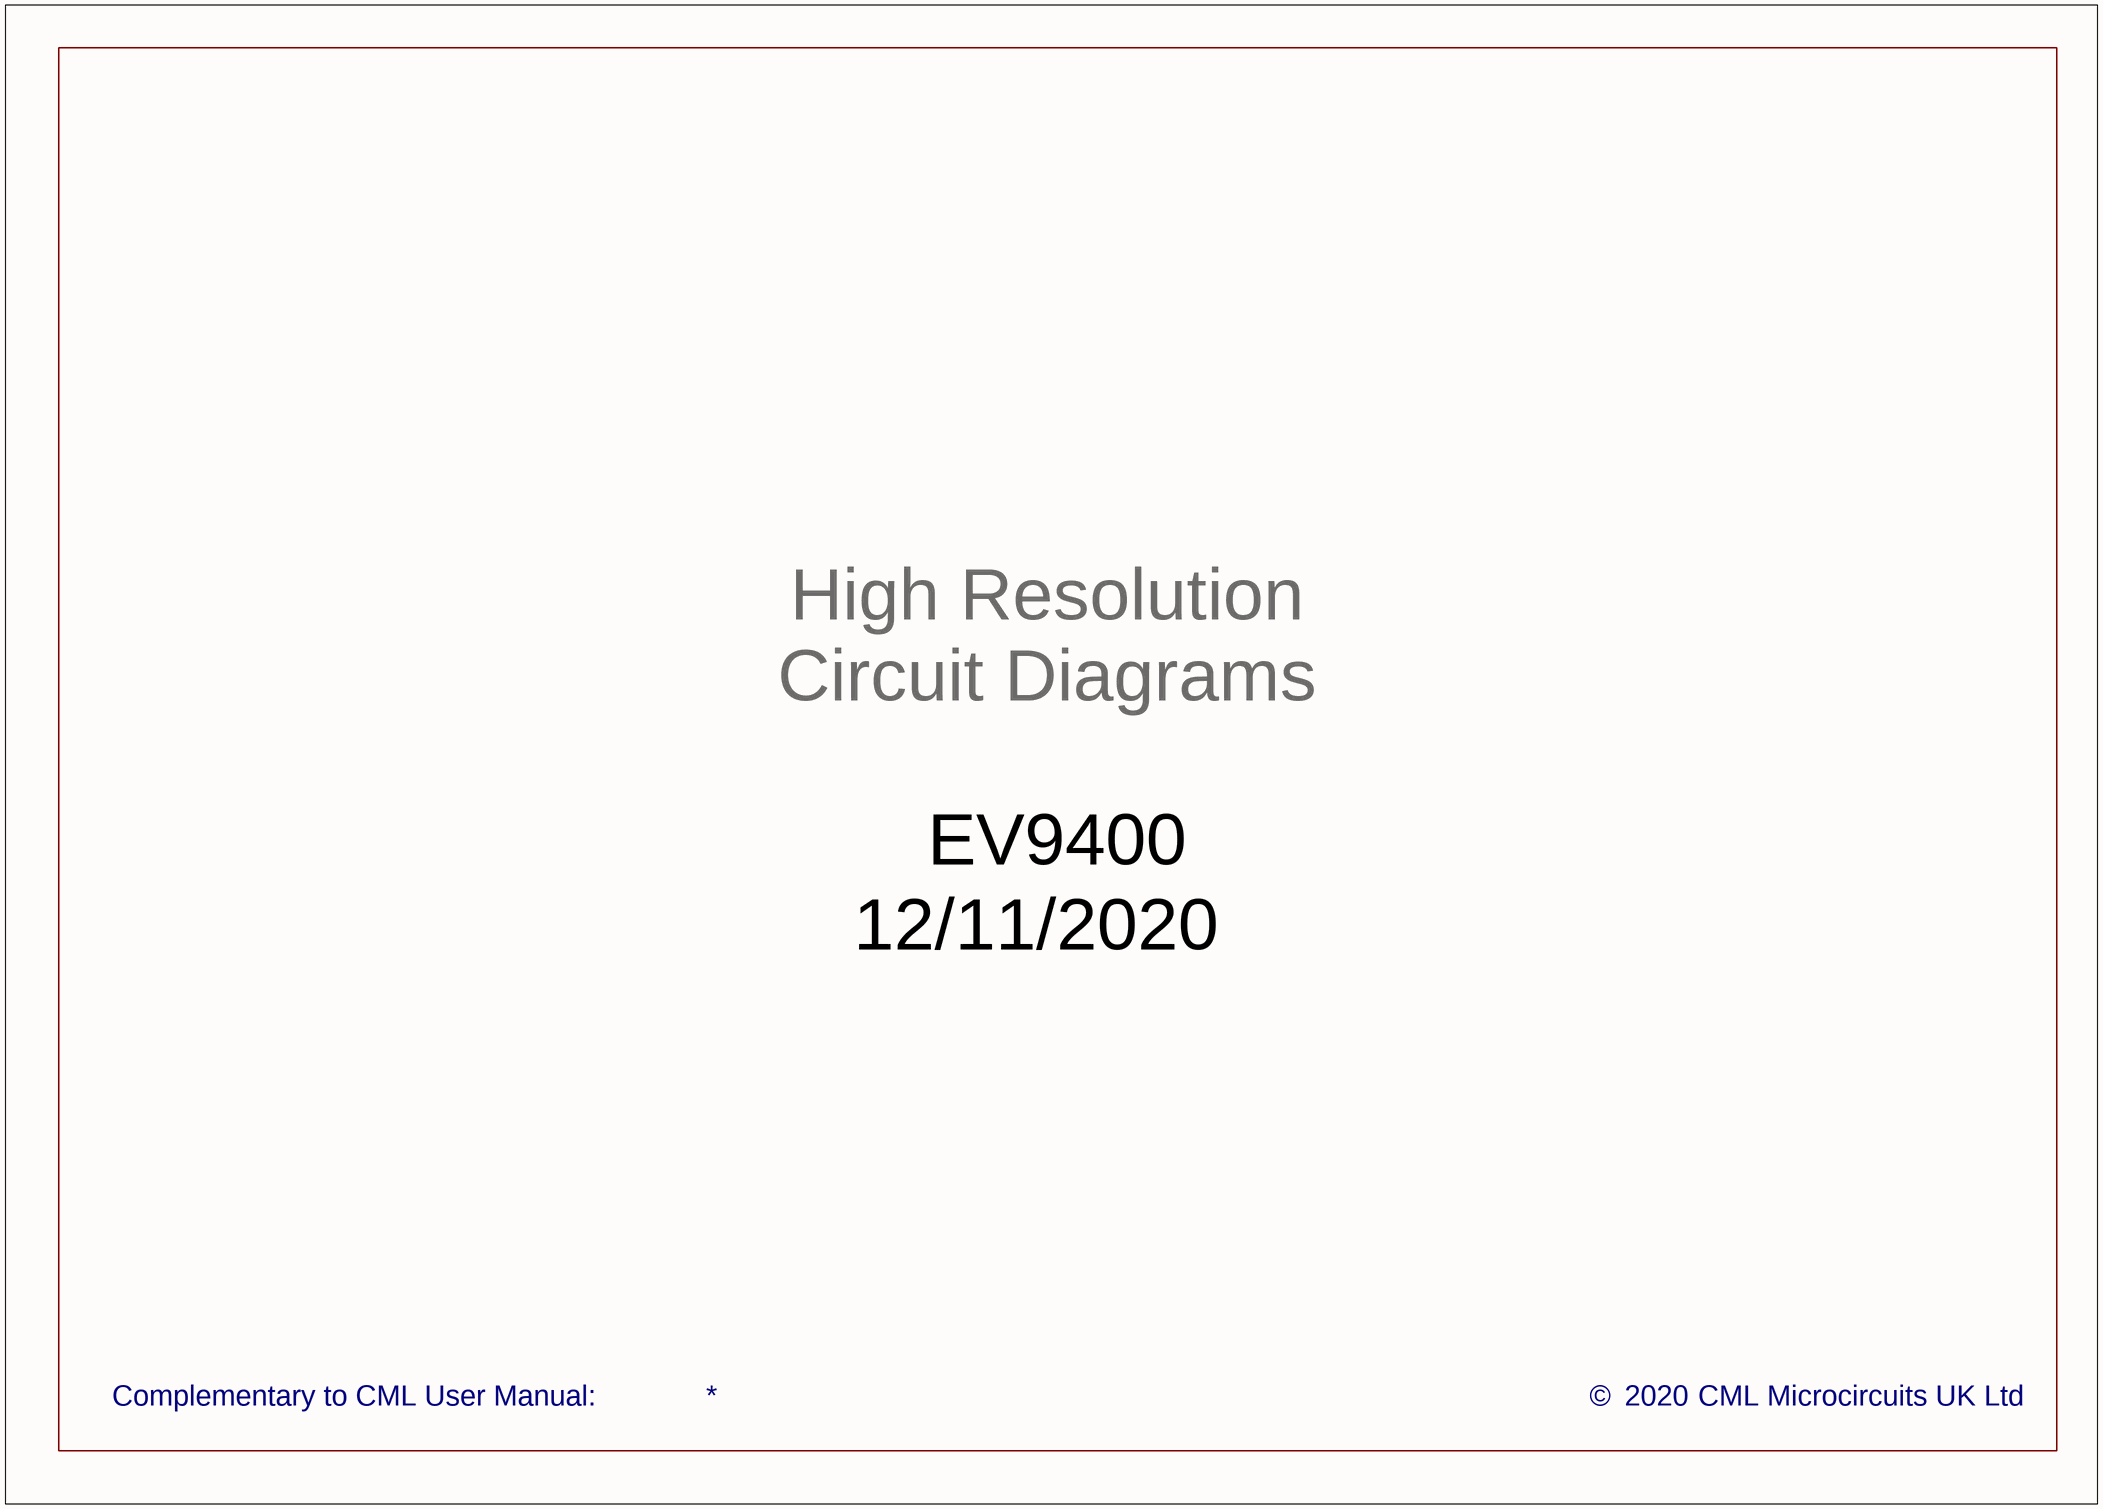
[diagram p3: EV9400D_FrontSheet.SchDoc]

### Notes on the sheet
- High Resolution
  Circuit Diagrams
  for
- Complementary to CML User Manual:
- ©

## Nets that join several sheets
5V_VCO: EV9400D_Power (JP2.2 TP3.1), EV9400D-CMX940 (R8.1)
AGND: EV9400D_Power (30 pins), EV9400D-CMX940 (76 pins)
AVDD_940: EV9400D_Power (JP4.2 TP5.1), EV9400D-CMX940 (9 pins)
DGND: EV9400D_Power (20 pins), EV9400D-CMX940 (6 pins)
DVDD3V3: EV9400D_Power (6 pins), EV9400D-CMX940 (R25.2)
CDATA: EV9400D_Power (C42.1 R33.1), EV9400D-CMX940 (U7.2)
CSN: EV9400D_Power (C43.1 R32.1), EV9400D-CMX940 (U7.4)
IRQN: EV9400D_Power (C39.1 R28.1 R37.1), EV9400D-CMX940 (U7.9)
MCLK: EV9400D_Power (C18.2), EV9400D-CMX940 (U7.15)
RDATA: EV9400D_Power (C40.1 R29.1 R35.1 TL6.1), EV9400D-CMX940 (U7.3)
REF_RESETN: EV9400D_Power (C66.1 R42.1 R48.2), EV9400D-CMX940 (U7.29)
RESETN: EV9400D_Power (C67.1 R26.1 R49.2), EV9400D-CMX940 (U7.47)
SCLK: EV9400D_Power (C41.1 R34.1), EV9400D-CMX940 (U7.5)
Test2: EV9400D_Power (C69.2), EV9400D-CMX940 (R53.2)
